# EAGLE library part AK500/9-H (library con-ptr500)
CONNECTOR Aug. 2004 / PTR Meßtechnik: Die Bezeichnung der Serie AK505 wurde geändert. Es handelt sich hierbei um AK500 in horizontaler Ausführung.
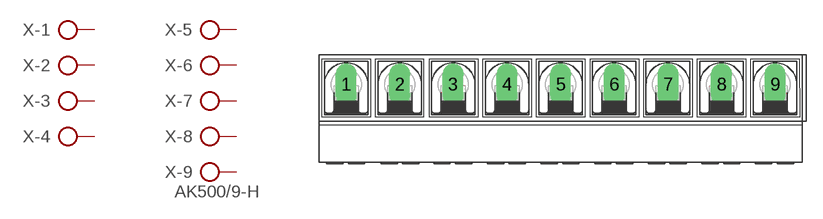
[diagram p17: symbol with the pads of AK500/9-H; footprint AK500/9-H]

Designator prefix X; gates -1=KL -2=KL -3=KL -4=KL -5=KL -6=KL -7=KL -8=KL -9=KLV

## AK500/9-H (OC_FARNELL: unknown; OC_NEWARK: unknown)  [AK500/9-H]
1  -1:KL  pas
2  -2:KL  pas
3  -3:KL  pas
4  -4:KL  pas
5  -5:KL  pas
6  -6:KL  pas
7  -7:KL  pas
8  -8:KL  pas
9  -9:KL  pas

## Footprint AK500/9-H (pad centres in mm)
CONNECTOR Aug. 2004 / PTR Meßtechnik: Die Bezeichnung der Serie AK505 wurde geändert. Es handelt sich hierbei um AK500 in horizontaler Ausführung.
drill 1.321 long: 1 -20.015,0; 2 -15.011,0; 3 -10.033,0; 4 -5.004,0; 5 0,0; 6 5.004,0; 7 10.033,0; 8 15.011,0; 9 20.015,0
